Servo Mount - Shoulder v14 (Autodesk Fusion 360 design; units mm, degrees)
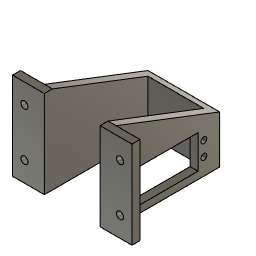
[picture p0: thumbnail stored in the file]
sketch "Sketch1" plane through (0, 0, 0) normal (0, 0, 1) x axis (1, 0, 0)
  line L1 (20, 0) -> (0, 0)
  line L2 (20, 65) -> (20, 0)
  line L3 (55, 65) -> (20, 65)
  line L4 (55, 0) -> (55, 65)
  line L5 (75, 0) -> (55, 0)
  line L6 (75, 5) -> (75, 0)
  line L7 (60, 5) -> (75, 5)
  line L8 (60, 70) -> (60, 5)
  line L9 (15, 70) -> (60, 70)
  line L10 (15, 5) -> (15, 70)
  line L11 (0, 5) -> (15, 5)
  line L12 (0, 0) -> (0, 5)
  point P1 (0, 0)
  point P2 (0, 0)
  coincident P1 P2
  horizontal L1
  perpendicular L1 L2
  perpendicular L2 L3
  perpendicular L1 L4
  perpendicular L4 L5
  perpendicular L5 L6
  perpendicular L6 L7
  perpendicular L7 L8
  perpendicular L8 L9
  perpendicular L9 L10
  perpendicular L10 L11
  perpendicular L11 L12
  dimension "d1" distance L2 L10 = 5
  dimension "d2" distance L4 L8 = 5 (= "d1")
  dimension "d3" distance L3 L9 = 5 (= "d1")
  dimension "d5" distance L1 L11 = 5 (= "d1")
  dimension "d6" distance L5 L7 = 5 (= "d1")
  dimension "d7" distance L4 L6 = 20
  dimension "d8" distance L2 L12 = 20 (= "d7")
  dimension "d9" distance L2 L4 = 35
  dimension "d10" distance L3 L5 = 65
extrude "Extrude1" new body sketch "Sketch1" along normal blind 30
sketch "Sketch2" plane through (60, 0, 0) normal (1, 0, 0) x axis (0, 1, 0)
  line L1 (70, 0) -> (5, 0)
  line L2 (70, 30) -> (70, 0)
  line L3 (5, 30) -> (70, 30)
  line L4 (5, 0) -> (5, 30)
  line L5 (0, 0) -> (65, 0)
  line L6 (0, 30) -> (0, 0)
  line L7 (65, 30) -> (0, 30)
  line L8 (65, 0) -> (65, 30)
  line L9 (5, 15) -> (65, 15)
  line L10 (35, 30) -> (35, 15)
  line L11 (61.8, 20.9852) -> (61.8, 24.4)
  line L12 (21.0078, 5) -> (45.15, 5)
  line L13 (61.8, 24.4) -> (61.8, 20.9852)
  curve K1 (8.2, 9.0148) -> (8.8, 8.544)
  line L14 (54.55, 25) -> (45.15, 25)
  line L15 (45.15, 25) -> (21.0078, 25)
  line L16 (8.2, 11.9852) -> (8.2, 18.0148)
  line L17 (8.8, 25) -> (15.45, 25)
  line L18 (21.0078, 25) -> (15.45, 25)
  line L19 (15.45, 5) -> (21.0078, 5)
  line L20 (8.8, 5) -> (15.45, 5)
  line L21 (54.55, 5) -> (15.45, 5)
  curve K2 (8.2, 20.9852) -> (8.8, 21.456)
  line L22 (15.45, 25) -> (54.55, 25)
  line L23 (8.2, 24.4) -> (8.2, 20.9852)
  line L24 (8.2, 9.0148) -> (8.2, 5.6)
  line L25 (61.2, 5) -> (54.55, 5)
  line L26 (8.2, 5.6) -> (8.2, 9.0148)
  curve K3 (61.2, 17.544) -> (61.8, 18.0148)
  curve K4 (61.2, 12.456) -> (61.8, 11.9852)
  line L27 (61.8, 11.9852) -> (61.8, 18.0148)
  line L28 (54.55, 5) -> (61.2, 5)
  line L29 (61.8, 18.0148) -> (61.8, 11.9852)
  line L30 (61.8, 9.0148) -> (61.8, 5.6)
  curve K5 (8.8, 17.544) -> (8.2, 18.0148)
  curve K6 (61.8, 18.0148) -> (61.2, 17.544)
  curve K7 (8.2, 18.0148) -> (8.8, 17.544)
  curve K8 (8.8, 21.456) -> (8.2, 20.9852)
  curve K9 (61.2, 21.456) -> (61.8, 20.9852)
  line L31 (15.45, 5) -> (8.8, 5)
  line L32 (61.2, 25) -> (54.55, 25)
  line L33 (8.2, 20.9852) -> (8.2, 24.4)
  curve K10 (61.2, 8.544) -> (61.8, 9.0148)
  curve K11 (8.2, 11.9852) -> (8.8, 12.456)
  curve K12 (61.8, 20.9852) -> (61.2, 21.456)
  curve K13 (61.8, 11.9852) -> (61.2, 12.456)
  line L34 (45.15, 5) -> (54.55, 5)
  line L35 (61.8, 5.6) -> (61.8, 9.0148)
  curve K14 (8.8, 8.544) -> (8.2, 9.0148)
  curve K15 (61.8, 9.0148) -> (61.2, 8.544)
  line L36 (8.2, 18.0148) -> (8.2, 11.9852)
  line L37 (54.55, 25) -> (61.2, 25)
  curve K16 (8.8, 12.456) -> (8.2, 11.9852)
  line L38 (15.45, 25) -> (8.8, 25)
  line L39 (56.5, 25.5) -> (14.5, 25.5)
  line L40 (56.5, 4.5) -> (56.5, 25.5)
  line L41 (14.5, 4.5) -> (56.5, 4.5)
  line L42 (14.5, 25.5) -> (14.5, 4.5)
  line L43 (14.5, 15) -> (56.5, 15)
  line L44 (35.5, 25.5) -> (35.5, 15)
  line L45 (8.2, 15) -> (61.8, 15)
  line L46 (35, 25) -> (35, 15)
  arc A1 centre (9.85, 10.5) radius 2.22 clockwise from (8.8, 12.456) to (8.8, 8.544)
  arc A2 centre (9.85, 10.5) radius 2.22 clockwise from (8.8, 12.456) to (8.8, 8.544)
  circle C1 centre (45.15, 15) radius 1.3
  circle C2 centre (45.15, 15) radius 3.292
  arc A3 centre (9.85, 19.5) radius 2.22 clockwise from (8.8, 21.456) to (8.8, 17.544)
  arc A4 centre (60.15, 10.5) radius 2.22 clockwise from (61.2, 8.544) to (61.2, 12.456)
  arc A5 centre (60.15, 10.5) radius 2.22 clockwise from (61.2, 8.544) to (61.2, 12.456)
  arc A6 centre (9.85, 19.5) radius 2.22 clockwise from (8.8, 21.456) to (8.8, 17.544)
  arc A7 centre (60.15, 19.5) radius 2.22 clockwise from (61.2, 17.544) to (61.2, 21.456)
  arc A8 centre (60.15, 19.5) radius 2.22 clockwise from (61.2, 17.544) to (61.2, 21.456)
  circle C3 centre (60.15, 19.5) radius 1.85
  circle C4 centre (60.15, 10.5) radius 1.85
  circle C5 centre (9.85, 19.5) radius 1.85
  circle C6 centre (9.85, 10.5) radius 1.85
  point P10 (65, 15)
  point P11 (5, 15)
  point P12 (35, 15)
  point P13 (35, 30)
  point P88 (56.5, 15)
  point P89 (14.5, 15)
  point P90 (35.5, 15)
  point P91 (35.5, 25.5)
  point P92 (61.8, 15)
  point P93 (8.2, 15)
  point P94 (35, 15)
  point P95 (35, 25)
  point P84 (14.5, 25.5)
  point P85 (56.5, 25.5)
  point P87 (14.5, 4.5)
  midpoint L8 P10
  midpoint L4 P11
  midpoint L9 P12
  coincident L7 P13
  horizontal L39
  vertical L40
  horizontal L41
  vertical L42
  midpoint L40 P88
  midpoint L42 P89
  midpoint L43 P90
  midpoint L39 P91
  midpoint L27 P92
  midpoint L16 P93
  perpendicular L16 L45
  midpoint L45 P94
  midpoint L22 P95
  perpendicular L15 L46
  concentric A7 C3
  concentric A5 C4
  concentric A3 C5
  concentric A2 C6
  dimension "d13" distance P84 P85 = 42
  dimension "d14" distance P84 P87 = 21
  dimension "d31" diameter C3 = 3.7
  dimension "d32" diameter C4 = 3.7 (= "d31")
  dimension "d34" diameter C6 = 3.7 (= "d31")
  dimension "d35" diameter C5 = 3.7 (= "d31")
extrude "Extrude2" cut sketch "Sketch2" profile of L39 L40 L41 L42 C3 C4 C5 C6 to an object
sketch "Sketch3" plane through (15, 0, 0) normal (-1, 0, 0) x axis (0, -1, 0)
  line L1 (-5, 0) -> (-70, 0)
  line L2 (-5, 30) -> (-5, 0)
  line L3 (-70, 30) -> (-5, 30)
  line L4 (-70, 0) -> (-70, 30)
  circle C1 centre (-45.15, 15) radius 1.3
  circle C2 centre (-45.15, 15) radius 3.292
  circle C3 centre (-45.15, 15) radius 2.15
  concentric C2 C3
  dimension "d17" diameter C3 = 4.3
extrude "Extrude3" cut sketch "Sketch3" profile of C3 to an object
sketch "Sketch4" plane through (0, 0, 30) normal (0, 0, 1) x axis (-1, 0, 0)
  line L1 (0, 0) -> (0, -5)
  line L2 (-20, 0) -> (0, 0)
  line L3 (-20, -65) -> (-20, 0)
  line L4 (-55, -65) -> (-20, -65)
  line L5 (-55, 0) -> (-55, -65)
  line L6 (-75, 0) -> (-55, 0)
  line L7 (-75, -5) -> (-75, 0)
  line L8 (-60, -5) -> (-75, -5)
  line L9 (-60, -70) -> (-60, -5)
  line L10 (-15, -70) -> (-60, -70)
  line L11 (-15, -5) -> (-15, -70)
  line L12 (0, -5) -> (-15, -5)
extrude "Extrude4" add sketch "Sketch4" along normal blind 25
sketch "Sketch5" plane through (75, 0, 0) normal (1, 0, 0) x axis (0, 1, 0)
  line L1 (5, 0) -> (0, 0)
  line L2 (5, 55) -> (5, 0)
  line L3 (0, 55) -> (5, 55)
  line L4 (0, 0) -> (0, 55)
  line L5 (14.5, 25.5) -> (14.5, 4.5)
  line L6 (56.5, 25.5) -> (14.5, 25.5)
  line L7 (56.5, 4.5) -> (56.5, 25.5)
  line L8 (14.5, 4.5) -> (56.5, 4.5)
  line L9 (70, 0) -> (5, 0)
  line L10 (70, 55) -> (70, 0)
  line L11 (5, 55) -> (70, 55)
  line L12 (5, 0) -> (5, 55)
  line L13 (70, 30) -> (5, 30)
  line L14 (5, 55) -> (70, 30)
  circle C1 centre (60.15, 10.5) radius 1.85
  circle C2 centre (9.85, 19.5) radius 1.85
  circle C3 centre (60.15, 19.5) radius 1.85
  circle C4 centre (9.85, 10.5) radius 1.85
  point P19 (70, 30)
  point P20 (70, 30)
  point P4 (5, 55)
  point P21 (5, 55)
  coincident P19 P20
  coincident P4 P21
extrude "Extrude5" cut sketch "Sketch5" profile of L10 L11 L14 to an object
sketch "Sketch6" plane through (0, 5, 0) normal (0, 1, 0) x axis (-1, 0, 0)
  line L1 (-60, 0) -> (-75, 0)
  line L2 (-60, 55) -> (-60, 0)
  line L3 (-75, 55) -> (-60, 55)
  line L4 (-75, 0) -> (-75, 55)
  line L5 (-67.5, 0) -> (-67.5, 55)
  line L6 (-75, 27.5) -> (-67.5, 27.5)
  line L7 (-60, 30) -> (-15, 30)
  line L8 (-60, 0) -> (-60, 30)
  line L9 (-15, 0) -> (-60, 0)
  line L10 (-15, 30) -> (-15, 0)
  line L11 (-37.5, 0) -> (-37.5, 30)
  circle C1 centre (-67.5, 42.5) radius 2.25
  circle C2 centre (-67.5, 12.5) radius 2.25
  circle C3 centre (-7.5, 42.5) radius 2.25
  circle C4 centre (-7.5, 12.5) radius 2.25
  point P6 (-67.5, 55)
  point P7 (-67.5, 0)
  point P8 (-67.5, 27.5)
  point P9 (-75, 27.5)
  point P10 (-67.5, 42.5)
  point P16 (-37.5, 30)
  point P17 (-37.5, 0)
  midpoint L3 P6
  midpoint L1 P7
  midpoint L5 P8
  midpoint L4 P9
  coincident L5 P10
  symmetric L6 C1 C2
  midpoint L7 P16
  midpoint L9 P17
  symmetric C1 L11 C3
  symmetric C2 L11 C4
  dimension "d27" diameter C1 = 4.5
  dimension "d28" distance L6 P10 = 15
extrude "Extrude6" cut sketch "Sketch6" profile of C1 C2 C3 C4 to an object
sketch "Sketch7" plane through (0, 0, 0) normal (0, -1, 0) x axis (1, 0, 0)
  line L1 (20, 0) -> (0, 0)
  line L2 (20, 55) -> (20, 0)
  line L3 (0, 55) -> (20, 55)
  line L4 (0, 0) -> (0, 55)
  line L5 (75, 0) -> (55, 0)
  line L6 (75, 55) -> (75, 0)
  line L7 (55, 55) -> (75, 55)
  line L8 (55, 0) -> (55, 55)
  line L9 (55, 4.5) -> (55, 25.5)
  line L10 (60, 4.5) -> (55, 4.5)
  line L11 (60, 25.5) -> (60, 4.5)
  line L12 (55, 25.5) -> (60, 25.5)
  line L13 (55, 15) -> (60, 15)
  circle C1 centre (7.5, 12.5) radius 2.25
  circle C2 centre (7.5, 42.5) radius 2.25
  circle C3 centre (67.5, 12.5) radius 2.25
  circle C4 centre (67.5, 42.5) radius 2.25
  point P18 (60, 15)
  point P19 (55, 15)
  midpoint L11 P18
  midpoint L9 P19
